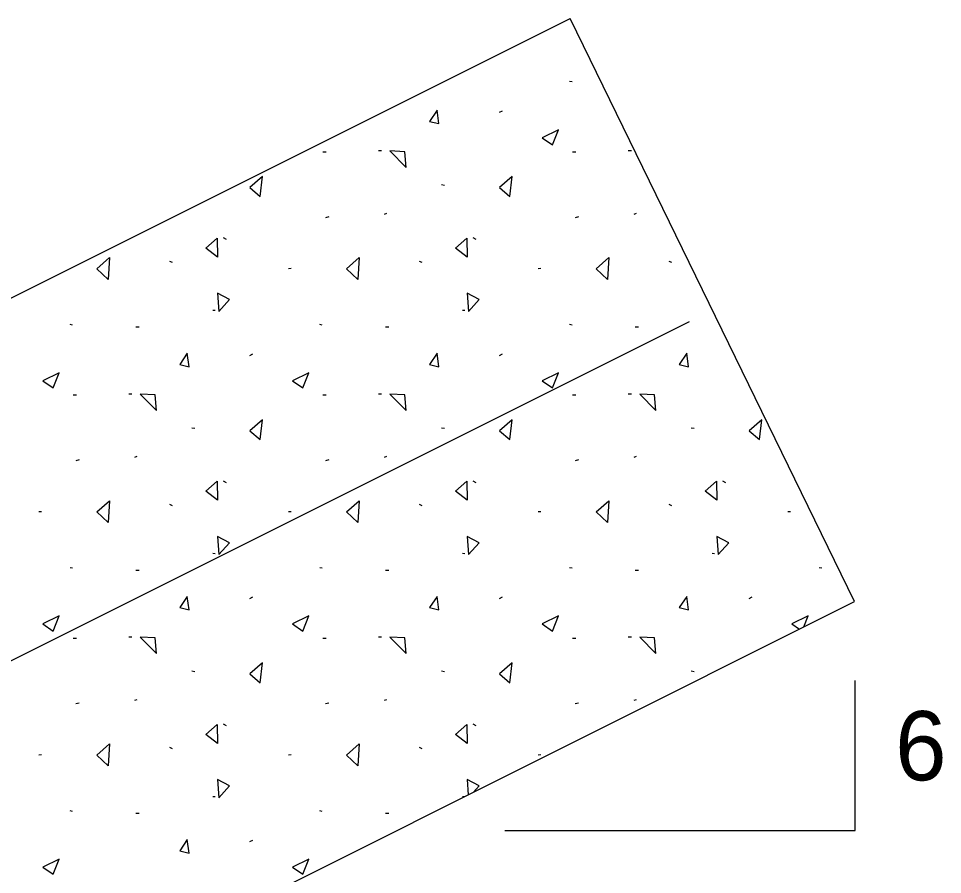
# Model space of a CAD drawing. Extents: x -48 to 108, y -5 to 100.
# Drawn here: x 69.164 to 74.147, y 25.936 to 30.554 of the extents above; entities that cross this region are included whole.
import ezdxf

# ---------------------------------------------------------------- set-up
doc = ezdxf.new("R2010")
doc.units = 0
for name, color, linetype in [('Level 2', 7, 'Continuous'), ('Level 25', 7, 'Continuous'), ('Level 44', 7, 'Continuous')]:
    doc.layers.add(name, color=color, linetype=linetype)

msp = doc.modelspace()

# ---------------------------------------------------------------- linework, layer by layer
at = {"layer": 'Level 2'}
msp.add_line((73.6729, 27.4077), (72.1385, 30.5536), dxfattribs=at)
at = {"layer": 'Level 25'}
for p, q in [((68.2659, 28.6174), (72.1385, 30.5536)), ((68.679, 26.8674), (72.7817, 28.9187)), ((69.0921, 25.1174), (73.6729, 27.4077))]:
    msp.add_line(p, q, dxfattribs=at)
at = {"layer": 'Level 44'}
for p, q in [((72.1489, 30.2113), (72.1356, 30.2136)), ((71.7716, 30.0543), (71.7556, 30.0463)), ((70.8236, 29.833), (70.8056, 29.833)), ((71.1222, 29.8393), (71.1052, 29.8393)), ((72.1702, 29.833), (72.1522, 29.833)), ((72.4689, 29.8393), (72.4519, 29.8393)), ((71.4616, 29.653), (71.4442, 29.656)), ((70.8379, 29.484), (70.8199, 29.479)), ((71.1486, 29.502), (71.1356, 29.497)), ((72.1846, 29.484), (72.1666, 29.479)), ((72.4952, 29.502), (72.4822, 29.497)), ((70.2846, 29.3606), (70.2696, 29.3696)), ((71.6312, 29.3606), (71.6162, 29.3696)), ((69.9942, 29.2366), (69.9799, 29.2433)), ((70.6339, 29.2046), (70.6192, 29.2033)), ((71.3409, 29.2366), (71.3266, 29.2433)), ((71.9806, 29.2046), (71.9659, 29.2033)), ((72.6876, 29.2366), (72.6732, 29.2433)), ((70.2246, 28.9776), (70.2112, 28.9786)), ((71.5712, 28.9776), (71.5579, 28.9786)), ((72.9068, 28.9785), (72.9046, 28.9786)), ((69.4556, 28.8996), (69.4422, 28.902)), ((69.8142, 28.8883), (69.7962, 28.8883)), ((70.8022, 28.8996), (70.7889, 28.902)), ((71.1609, 28.8883), (71.1429, 28.8883)), ((72.1489, 28.8996), (72.1356, 28.902)), ((72.5076, 28.8883), (72.4896, 28.8883)), ((70.4249, 28.7426), (70.4089, 28.7346)), ((71.7716, 28.7426), (71.7556, 28.7346)), ((69.4769, 28.5213), (69.4589, 28.5213)), ((69.7756, 28.5276), (69.7586, 28.5276)), ((70.8236, 28.5213), (70.8056, 28.5213)), ((71.1222, 28.5276), (71.1052, 28.5276)), ((72.1702, 28.5213), (72.1522, 28.5213)), ((72.4689, 28.5276), (72.4519, 28.5276)), ((70.1149, 28.3413), (70.0976, 28.3443)), ((71.4616, 28.3413), (71.4442, 28.3443)), ((72.8082, 28.3413), (72.7909, 28.3443)), ((69.4912, 28.1723), (69.4732, 28.1673)), ((69.8019, 28.1903), (69.7889, 28.1853)), ((70.8379, 28.1723), (70.8199, 28.1673)), ((71.1486, 28.1903), (71.1356, 28.1853)), ((72.1846, 28.1723), (72.1666, 28.1673)), ((72.4952, 28.1903), (72.4822, 28.1853)), ((70.2846, 28.049), (70.2696, 28.058)), ((71.6312, 28.049), (71.6162, 28.058)), ((72.9779, 28.049), (72.9629, 28.058)), ((69.9942, 27.925), (69.9799, 27.9316)), ((71.3409, 27.925), (71.3266, 27.9316)), ((72.6876, 27.925), (72.6732, 27.9316)), ((69.2872, 27.893), (69.2726, 27.8916)), ((70.6339, 27.893), (70.6192, 27.8916)), ((71.9806, 27.893), (71.9659, 27.8916)), ((73.3272, 27.893), (73.3126, 27.8916)), ((70.2246, 27.666), (70.2112, 27.667)), ((71.5712, 27.666), (71.5579, 27.667)), ((72.9179, 27.666), (72.9046, 27.667)), ((69.4556, 27.588), (69.4422, 27.5903)), ((69.8142, 27.5766), (69.7962, 27.5766)), ((70.8022, 27.588), (70.7889, 27.5903)), ((71.1609, 27.5766), (71.1429, 27.5766)), ((72.1489, 27.588), (72.1356, 27.5903)), ((72.5076, 27.5766), (72.4896, 27.5766)), ((73.4956, 27.588), (73.4822, 27.5903)), ((70.4249, 27.431), (70.4089, 27.423)), ((71.7716, 27.431), (71.7556, 27.423)), ((73.1182, 27.431), (73.1022, 27.423)), ((69.7756, 27.216), (69.7586, 27.216)), ((71.1222, 27.216), (71.1052, 27.216)), ((72.4689, 27.216), (72.4519, 27.216)), ((69.4769, 27.2096), (69.4589, 27.2096)), ((70.8236, 27.2096), (70.8056, 27.2096)), ((72.1702, 27.2096), (72.1522, 27.2096)), ((70.1149, 27.0296), (70.0976, 27.0326)), ((71.4616, 27.0296), (71.4442, 27.0326)), ((72.8082, 27.0296), (72.7909, 27.0326)), ((73.6764, 26.1723), (73.6764, 26.9831)), ((69.8019, 26.8786), (69.7889, 26.8736)), ((71.1486, 26.8786), (71.1356, 26.8736)), ((72.4952, 26.8786), (72.4822, 26.8736)), ((69.4912, 26.8606), (69.4732, 26.8556)), ((70.8379, 26.8606), (70.8199, 26.8556)), ((72.1846, 26.8606), (72.1666, 26.8556)), ((70.2846, 26.7373), (70.2696, 26.7463)), ((71.6312, 26.7373), (71.6162, 26.7463)), ((69.9942, 26.6133), (69.9799, 26.62)), ((71.3409, 26.6133), (71.3266, 26.62)), ((69.2872, 26.5813), (69.2726, 26.58)), ((70.6339, 26.5813), (70.6192, 26.58)), ((71.9806, 26.5813), (71.9659, 26.58)), ((70.2246, 26.3543), (70.2112, 26.3553)), ((71.5667, 26.3546), (71.5579, 26.3553)), ((69.4556, 26.2763), (69.4422, 26.2786)), ((69.8142, 26.265), (69.7962, 26.265)), ((70.8022, 26.2763), (70.7889, 26.2786)), ((71.1609, 26.265), (71.1429, 26.265)), ((71.7859, 26.1723), (73.6764, 26.1723)), ((70.4249, 26.1193), (70.4089, 26.1113))]:
    msp.add_line(p, q, dxfattribs=at)
for points in [[(71.4302, 29.9866), (71.4209, 30.0596), (71.3799, 29.9986)], [(72.0442, 29.872), (72.0759, 29.9536), (71.9876, 29.9106)], [(71.2472, 29.835), (71.1672, 29.8393), (71.2539, 29.7506)], [(70.4789, 29.701), (70.4106, 29.6413), (70.4672, 29.5936)], [(71.8256, 29.701), (71.7572, 29.6413), (71.8139, 29.5936)], [(70.2372, 29.2663), (70.1732, 29.3146), (70.2346, 29.369)], [(71.5839, 29.2663), (71.5199, 29.3146), (71.5812, 29.369)], [(69.6476, 29.146), (69.5859, 29.203), (69.6542, 29.264)], [(70.9942, 29.146), (70.9326, 29.203), (71.0009, 29.264)], [(72.3409, 29.146), (72.2792, 29.203), (72.3476, 29.264)], [(70.2439, 28.973), (70.3009, 29.037), (70.2372, 29.071)], [(71.5906, 28.973), (71.6476, 29.037), (71.5839, 29.071)], [(70.0836, 28.675), (70.0742, 28.748), (70.0332, 28.687)], [(71.4302, 28.675), (71.4209, 28.748), (71.3799, 28.687)], [(72.7769, 28.675), (72.7676, 28.748), (72.7266, 28.687)], [(69.3509, 28.5603), (69.3826, 28.642), (69.2942, 28.599)], [(70.6976, 28.5603), (70.7292, 28.642), (70.6409, 28.599)], [(72.0442, 28.5603), (72.0759, 28.642), (71.9876, 28.599)], [(69.9006, 28.5233), (69.8206, 28.5276), (69.9072, 28.439)], [(71.2472, 28.5233), (71.1672, 28.5276), (71.2539, 28.439)], [(72.5939, 28.5233), (72.5139, 28.5276), (72.6006, 28.439)], [(70.4789, 28.3893), (70.4106, 28.3296), (70.4672, 28.282)], [(71.8256, 28.3893), (71.7572, 28.3296), (71.8139, 28.282)], [(73.1722, 28.3893), (73.1039, 28.3296), (73.1606, 28.282)], [(70.2372, 27.9546), (70.1732, 28.003), (70.2346, 28.0573)], [(71.5839, 27.9546), (71.5199, 28.003), (71.5812, 28.0573)], [(72.9306, 27.9546), (72.8666, 28.003), (72.9279, 28.0573)], [(69.6476, 27.8343), (69.5859, 27.8913), (69.6542, 27.9523)], [(70.9942, 27.8343), (70.9326, 27.8913), (71.0009, 27.9523)], [(72.3409, 27.8343), (72.2792, 27.8913), (72.3476, 27.9523)], [(70.2439, 27.6613), (70.3009, 27.7253), (70.2372, 27.7593)], [(71.5906, 27.6613), (71.6476, 27.7253), (71.5839, 27.7593)], [(72.9372, 27.6613), (72.9942, 27.7253), (72.9306, 27.7593)], [(70.0836, 27.3633), (70.0742, 27.4363), (70.0332, 27.3753)], [(71.4302, 27.3633), (71.4209, 27.4363), (71.3799, 27.3753)], [(72.7769, 27.3633), (72.7676, 27.4363), (72.7266, 27.3753)], [(69.3509, 27.2486), (69.3826, 27.3303), (69.2942, 27.2873)], [(70.6976, 27.2486), (70.7292, 27.3303), (70.6409, 27.2873)], [(72.0442, 27.2486), (72.0759, 27.3303), (71.9876, 27.2873)], [(69.9006, 27.2116), (69.8206, 27.216), (69.9072, 27.1273)], [(71.2472, 27.2116), (71.1672, 27.216), (71.2539, 27.1273)], [(72.5939, 27.2116), (72.5139, 27.216), (72.6006, 27.1273)], [(70.4789, 27.0776), (70.4106, 27.018), (70.4672, 26.9703)], [(71.8256, 27.0776), (71.7572, 27.018), (71.8139, 26.9703)], [(70.2372, 26.643), (70.1732, 26.6913), (70.2346, 26.7456)], [(71.5839, 26.643), (71.5199, 26.6913), (71.5812, 26.7456)], [(69.6476, 26.5226), (69.5859, 26.5796), (69.6542, 26.6406)], [(70.9942, 26.5226), (70.9326, 26.5796), (71.0009, 26.6406)], [(70.2439, 26.3496), (70.3009, 26.4136), (70.2372, 26.4476)], [(70.0836, 26.0516), (70.0742, 26.1246), (70.0332, 26.0636)], [(69.3509, 25.937), (69.3826, 26.0186), (69.2942, 25.9756)], [(70.6976, 25.937), (70.7292, 26.0186), (70.6409, 25.9756)]]:
    msp.add_lwpolyline(points, close=True, dxfattribs=at)
for points in [[(73.3996, 27.2711), (73.4226, 27.3303), (73.3342, 27.2873), (73.3756, 27.2591)], [(71.6178, 26.3802), (71.6476, 26.4136), (71.5839, 26.4476), (71.5894, 26.366)]]:
    msp.add_lwpolyline(points, dxfattribs=at)

# ---------------------------------------------------------------- texts
at = {"layer": 'Level 25'}
msp.add_text('6', height=0.3733, dxfattribs=at).set_placement((73.8914, 26.4439))

doc.saveas('drawing.dxf')
